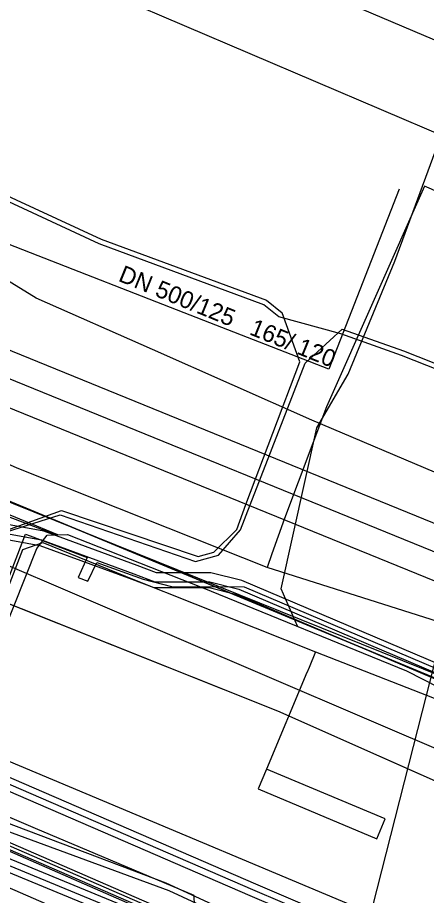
# Model space of a CAD drawing. Extents: x -596024 to -594475, y -1163820 to -1161957.
# Drawn here: x -594693.78 to -594674.72, y -1162231.56 to -1162190.62 of the extents above; entities that cross this region are included whole.
import ezdxf

# ---------------------------------------------------------------- set-up
doc = ezdxf.new("R2010")
doc.units = 0
for name, color, linetype in [('Level 1', 7, 'Continuous'), ('Vrstva 1', 7, 'Continuous'), ('Vrstva 10', 7, 'Continuous'), ('Vrstva 12', 7, 'Continuous'), ('Vrstva 13', 7, 'Continuous'), ('Vrstva 19', 7, 'Continuous'), ('Vrstva 29', 7, 'Continuous'), ('Vrstva 30', 7, 'Continuous'), ('Vrstva 32', 7, 'Continuous'), ('Vrstva 42', 7, 'Continuous'), ('Vrstva 44', 7, 'Continuous'), ('Vrstva 55', 7, 'Continuous'), ('Vrstva 58', 7, 'Continuous'), ('Vrstva 9', 7, 'Continuous')]:
    doc.layers.add(name, color=color, linetype=linetype)

msp = doc.modelspace()

# ---------------------------------------------------------------- linework, layer by layer
at = {"layer": 'Level 1'}
msp.add_lwpolyline([(-594750.45, -1162195.55), (-594709.77, -1162211.75), (-594681.66, -1162222.95), (-594639.16, -1162241.84), (-594604.2, -1162257.38), (-594561.16, -1162275.84)], dxfattribs=at)
at = {"layer": 'Vrstva 1'}
for points in [[(-594709.77, -1162211.75), (-594707.04, -1162212.84), (-594697.64, -1162216.58), (-594681.66, -1162222.95)], [(-594681.66, -1162222.95), (-594661.62, -1162231.86), (-594655.18, -1162234.72), (-594641.16, -1162240.95), (-594639.16, -1162241.84)]]:
    msp.add_lwpolyline(points, dxfattribs=at)
at = {"layer": 'Vrstva 10'}
for points in [[(-594718.121, -1162215.685), (-594682.698, -1162231.026), (-594673.018, -1162235.167), (-594642.251, -1162248.515)], [(-594642.489, -1162249.065), (-594673.256, -1162235.718), (-594682.935, -1162231.577), (-594718.359, -1162216.235)], [(-594669.097, -1162240.596), (-594676.92, -1162237.095), (-594687.944, -1162232.423), (-594698.459, -1162228.081), (-594703.881, -1162225.994), (-594707.851, -1162224.099), (-594708.531, -1162223.765)], [(-594669.343, -1162241.144), (-594677.16, -1162237.645), (-594688.176, -1162232.977), (-594698.681, -1162228.639), (-594704.119, -1162226.546), (-594708.109, -1162224.641), (-594708.769, -1162224.315)]]:
    msp.add_lwpolyline(points, dxfattribs=at)
at = {"layer": 'Vrstva 12'}
for points in [[(-594709.79, -1162161.71), (-594711.19, -1162161.15), (-594711.71, -1162161.2), (-594720.54, -1162182.38), (-594720.76, -1162182.87), (-594723.51, -1162188.28), (-594727.58, -1162199.36), (-594715.62, -1162204.79), (-594697, -1162212.84), (-594691.98, -1162214.75)], [(-594687.5, -1162206.1), (-594692.91, -1162203.71), (-594698.08, -1162200.54), (-594701.97, -1162199.62), (-594703.17, -1162199.89), (-594736.07, -1162186.08), (-594790.15, -1162162.04)], [(-594680.74, -1162219.01), (-594681.49, -1162217.26), (-594679.84, -1162209.75), (-594678.37, -1162207.25), (-594676.2, -1162201.98), (-594672.39, -1162191.66), (-594669.77, -1162185.57), (-594666.54, -1162176.61), (-594662.03, -1162166.78)], [(-594691.9, -1162214.74), (-594693.41, -1162214.13), (-594708.66, -1162207.82), (-594726.57, -1162199.83), (-594745.03, -1162192.17), (-594754.89, -1162188.06), (-594753.69, -1162185.32)], [(-594767.38, -1162194.31), (-594722.65, -1162213.34), (-594687.5, -1162228.11)], [(-594669.22, -1162240.87), (-594677.04, -1162237.37), (-594688.06, -1162232.7), (-594698.57, -1162228.36), (-594704, -1162226.27), (-594707.98, -1162224.37), (-594708.65, -1162224.04), (-594716.25, -1162220.76), (-594733.56, -1162213.39), (-594745.1, -1162208.5), (-594754.35, -1162204.63), (-594755.28, -1162204.24), (-594755.87, -1162204), (-594756.43, -1162203.77), (-594756.78, -1162203.62), (-594757.22, -1162203.43), (-594757.54, -1162203.32), (-594758.33, -1162202.96), (-594758.77, -1162202.76), (-594758.93, -1162202.52), (-594760.19, -1162200.82), (-594760.82, -1162199.87)], [(-594673.84, -1162212.04), (-594680.06, -1162209.4), (-594687.5, -1162206.1)], [(-594701.93, -1162231.57), (-594700.22, -1162232.12), (-594699.53, -1162232.3), (-594698.85, -1162231.48), (-594698.82, -1162230.28), (-594692.89, -1162215.39), (-594692.41, -1162214.76), (-594691.46, -1162214.73), (-594685.17, -1162217.2), (-594675.66, -1162221.09), (-594674.13, -1162221.87), (-594673.14, -1162222.77), (-594660.42, -1162228.26), (-594659.07, -1162228.75), (-594653.33, -1162230.97), (-594645.81, -1162234.32), (-594640.49, -1162236.32), (-594633.61, -1162239.41), (-594630.67, -1162240.39), (-594630.22, -1162240.14), (-594629.84, -1162239.45)], [(-594701.93, -1162231.57), (-594700.22, -1162232.12), (-594699.53, -1162232.3), (-594698.85, -1162231.48), (-594698.82, -1162230.28), (-594692.89, -1162215.39), (-594692.41, -1162214.76), (-594691.46, -1162214.73), (-594685.17, -1162217.2), (-594675.66, -1162221.09), (-594674.13, -1162221.87), (-594673.14, -1162222.77), (-594660.42, -1162228.26), (-594659.07, -1162228.75), (-594653.33, -1162230.97), (-594645.81, -1162234.32), (-594640.49, -1162236.32), (-594633.61, -1162239.41), (-594630.67, -1162240.39), (-594630.22, -1162240.14), (-594629.84, -1162239.45)], [(-594687.5, -1162228.11), (-594635.41, -1162250)]]:
    msp.add_lwpolyline(points, dxfattribs=at)
at = {"layer": 'Vrstva 13'}
msp.add_line((-594825.39, -1162131.442), (-594661.497, -1162201.455), dxfattribs=at)
for points in [[(-595078.908, -1162012.46), (-595067.73, -1162017.42), (-595065.08, -1162018.44), (-594997.08, -1162047.37), (-594955.55, -1162065.41), (-594939.29, -1162072.9), (-594936.52, -1162074.16), (-594923.87, -1162075.93), (-594910.2, -1162085.83), (-594902.18, -1162091.86), (-594900.73, -1162093.05), (-594899.52, -1162093.99), (-594898.81, -1162094.53), (-594891.57, -1162097.97), (-594883.253, -1162101.678), (-594870.37, -1162107.41), (-594778.03, -1162146.97), (-594708.7, -1162177.08), (-594658.923, -1162198.2)], [(-594836.23, -1162155.443), (-594836.196, -1162155.782), (-594816.247, -1162164.384), (-594814.935, -1162164.957), (-594803.879, -1162169.64), (-594755.473, -1162190.086), (-594744.01, -1162194.87), (-594731.121, -1162200.339), (-594730.015, -1162200.811), (-594704.47, -1162211.75), (-594699.45, -1162213.94), (-594673.314, -1162225.133)]]:
    msp.add_lwpolyline(points, dxfattribs=at)
at = {"layer": 'Vrstva 19'}
for points in [[(-594695.25, -1162276.17), (-594690.21, -1162265.28), (-594680.2, -1162243.33), (-594679.351, -1162240.241), (-594678.82, -1162238.33), (-594678.078, -1162235.421), (-594674.9, -1162222.97), (-594673.86, -1162218.9), (-594682.15, -1162216.27), (-594693.73, -1162211.66), (-594707.83, -1162205.54), (-594713.34, -1162203.16), (-594714.6, -1162202.61), (-594730.47, -1162196.31), (-594740.5, -1162192.55), (-594751.07, -1162187.95), (-594753.63, -1162189.06), (-594775.09, -1162179.85), (-594776.07, -1162176.84), (-594793.1, -1162168.81), (-594802.09, -1162164.76), (-594816.08, -1162158.49), (-594834.13, -1162150.42), (-594853.67, -1162141.96)], [(-594685.55, -1162231.56), (-594692.94, -1162228.45), (-594699.49, -1162225.65), (-594749.98, -1162204.19), (-594785.76, -1162188.98), (-594797.35, -1162184.05)], [(-594673.7, -1162198.99), (-594674.48, -1162198.63), (-594674.81, -1162198.49), (-594679.38, -1162208.77), (-594681.34, -1162213.98), (-594681.93, -1162215.63), (-594682.15, -1162216.27)], [(-594672.02, -1162237.58), (-594672.39, -1162237.76), (-594674.91, -1162239.83), (-594676.98, -1162240.84), (-594678.73, -1162240.33), (-594678.81, -1162240.31), (-594679.02, -1162240.26), (-594679.43, -1162240.18), (-594679.63, -1162240.15), (-594679.77, -1162240.12), (-594682.47, -1162239.25), (-594684.29, -1162236.54), (-594684.66, -1162235.21), (-594685.53, -1162232.03), (-594685.55, -1162231.56)]]:
    msp.add_lwpolyline(points, dxfattribs=at)
at = {"layer": 'Vrstva 29'}
msp.add_lwpolyline([(-594527.721, -1162116.547), (-594550.035, -1162144.733), (-594618.49, -1162117.698), (-594660.636, -1162221.142), (-594706.437, -1162202.481)], dxfattribs=at)
at = {"layer": 'Vrstva 30'}
for points in [[(-594706.74, -1162201.008), (-594661.322, -1162219.513), (-594619.181, -1162116.081), (-594550.439, -1162143.229), (-594528.701, -1162115.771)], [(-594526.741, -1162117.323), (-594549.631, -1162146.237), (-594617.799, -1162119.315), (-594659.95, -1162222.771), (-594706.133, -1162203.955)]]:
    msp.add_lwpolyline(points, dxfattribs=at)
at = {"layer": 'Vrstva 42'}
for points in [[(-594841.22, -1162164.89), (-594841.55, -1162165.818), (-594823.941, -1162173.342), (-594805.527, -1162181.255), (-594786.096, -1162189.732), (-594763.998, -1162199.133), (-594752.438, -1162204.617), (-594739.102, -1162210.309), (-594723.16, -1162216.972), (-594709.798, -1162222.556), (-594699.416, -1162226.808), (-594686.936, -1162232.243), (-594670.535, -1162239.442), (-594642.912, -1162251.21), (-594626.307, -1162258.207), (-594595.818, -1162271.123), (-594582.146, -1162276.922), (-594568.678, -1162282.65), (-594548.298, -1162291.531), (-594530.464, -1162298.451), (-594511.972, -1162306.232), (-594493.611, -1162313.902), (-594475.47, -1162321.871)], [(-594805, -1162180.3), (-594805.561, -1162181.567), (-594805.473, -1162181.605), (-594786.214, -1162190.008), (-594764.122, -1162199.407), (-594752.562, -1162204.891), (-594739.218, -1162210.585), (-594723.276, -1162217.248), (-594709.912, -1162222.834), (-594699.532, -1162227.084), (-594687.056, -1162232.517), (-594670.655, -1162239.718), (-594643.03, -1162251.486), (-594626.423, -1162258.483), (-594595.936, -1162271.399), (-594582.264, -1162277.198), (-594568.796, -1162282.926), (-594548.412, -1162291.809), (-594530.576, -1162298.729), (-594512.088, -1162306.508), (-594493.729, -1162314.178), (-594475.47, -1162322.199)], [(-594475.47, -1162322.035), (-594492.486, -1162314.56), (-594509.999, -1162307.221), (-594528.715, -1162299.349), (-594548.355, -1162291.67), (-594568.737, -1162282.788), (-594582.205, -1162277.06), (-594595.877, -1162271.261), (-594626.365, -1162258.345), (-594642.971, -1162251.348), (-594670.595, -1162239.58), (-594686.996, -1162232.38), (-594699.474, -1162226.946), (-594709.855, -1162222.695), (-594723.218, -1162217.11), (-594739.16, -1162210.447), (-594752.5, -1162204.754), (-594764.06, -1162199.27), (-594786.155, -1162189.87), (-594805.5, -1162181.43)], [(-594615.74, -1162262.79), (-594624.65, -1162259.07), (-594637.95, -1162253.48), (-594653.13, -1162246.96), (-594666.17, -1162241.28), (-594679.92, -1162235.52), (-594687.43, -1162232.45), (-594694.39, -1162229.4), (-594701, -1162226.48), (-594711.77, -1162221.9), (-594718.09, -1162219.27), (-594728.65, -1162214.76), (-594737.08, -1162211.18), (-594746.93, -1162206.99), (-594753.92, -1162203.71), (-594761.99, -1162200.35), (-594768.71, -1162197.49), (-594777.63, -1162193.65), (-594785.3, -1162190.25), (-594792.89, -1162187), (-594796.23, -1162185.84), (-594796.51, -1162185.77), (-594796.81, -1162185.85)], [(-594699.54, -1162231.03), (-594693.54, -1162215.43), (-594692.61, -1162215.1), (-594688.33, -1162216.85), (-594679.89, -1162220.2)], [(-594679.89, -1162220.2), (-594680.19, -1162220.93), (-594680.3, -1162221.18)], [(-594679.89, -1162220.2), (-594674.37, -1162222.37), (-594672.114, -1162223.265)], [(-594680.291, -1162221.159), (-594682.183, -1162225.678), (-594682.569, -1162226.6), (-594677.034, -1162228.917), (-594676.648, -1162227.995), (-594682.183, -1162225.678)]]:
    msp.add_lwpolyline(points, dxfattribs=at)
at = {"layer": 'Vrstva 44'}
for points in [[(-594615.489, -1162264.329), (-594617.876, -1162263.185), (-594624.753, -1162260.392), (-594653.042, -1162248.004), (-594673.87, -1162239.439), (-594676.32, -1162238.996), (-594700.937, -1162228.271), (-594701.517, -1162227.634), (-594706.4, -1162225.55), (-594708.626, -1162224.544), (-594732.851, -1162213.96), (-594749.58, -1162206.904), (-594751.558, -1162206.159), (-594757.592, -1162203.739), (-594760.561, -1162201.965), (-594774.949, -1162195.637), (-594776.33, -1162195.028), (-594780.641, -1162193.061), (-594785.301, -1162190.858), (-594797.218, -1162185.869), (-594798.27, -1162185.406), (-594820.513, -1162176.019), (-594846.169, -1162165.001), (-594853.363, -1162161.962)], [(-594717.114, -1162188.761), (-594696.98, -1162197.67), (-594689.88, -1162200.96), (-594682.185, -1162203.807), (-594681.454, -1162204.395)], [(-594710.511, -1162246.121), (-594706.724, -1162241.317), (-594700.171, -1162229.614), (-594694.505, -1162214.613), (-594691.734, -1162213.615), (-594685.364, -1162215.761), (-594684.632, -1162215.557), (-594683.554, -1162214.497), (-594683.14, -1162213.325), (-594680.629, -1162206.672), (-594681.454, -1162204.395)], [(-594710.389, -1162246.171), (-594706.656, -1162241.485), (-594700.077, -1162229.706), (-594694.291, -1162214.612), (-594691.804, -1162213.81), (-594685.493, -1162215.996), (-594684.419, -1162215.691), (-594683.384, -1162214.508), (-594682.942, -1162213.351), (-594680.38, -1162206.736), (-594678.644, -1162205.16)], [(-594678.644, -1162205.16), (-594675.8, -1162206.17), (-594668.05, -1162209.23), (-594663.13, -1162210.88), (-594651.32, -1162215.21), (-594641.28, -1162219.24), (-594633.977, -1162221.217), (-594633.824, -1162221.643), (-594634.056, -1162222.424)], [(-594614.41, -1162261.91), (-594621.99, -1162258.58), (-594628.37, -1162255.68), (-594636.04, -1162252.82), (-594642.94, -1162249.7), (-594656.3, -1162244), (-594663.1, -1162240.9), (-594670.56, -1162238.06), (-594678.56, -1162234.81), (-594686.86, -1162230.99), (-594695.45, -1162227.75), (-594696.12, -1162227.93), (-594696.75, -1162228.24), (-594697.24, -1162228.82), (-594697.77, -1162230.04), (-594699.66, -1162234.68), (-594702.47, -1162240.02), (-594704.27, -1162242.54), (-594705.7, -1162243.65), (-594707.64, -1162244.5), (-594708.77, -1162244.96), (-594709.91, -1162246.4), (-594710.539, -1162247.725)], [(-594710.243, -1162247.851), (-594709.62, -1162246.52), (-594708.65, -1162245.21), (-594707.44, -1162244.71), (-594705.54, -1162243.89), (-594704.05, -1162242.67), (-594702.2, -1162240.18), (-594699.38, -1162234.79), (-594697.5, -1162230.19), (-594696.67, -1162228.8), (-594696.02, -1162228.26), (-594695.41, -1162228.16), (-594695.4, -1162228.15), (-594686.73, -1162231.34), (-594678.69, -1162235.07), (-594670.68, -1162238.26), (-594662.6, -1162241.59), (-594656.44, -1162244.41), (-594643.09, -1162250), (-594636.37, -1162253.13), (-594628.37, -1162256.91), (-594622.62, -1162258.99), (-594614.48, -1162262.29)]]:
    msp.add_lwpolyline(points, dxfattribs=at)
at = {"layer": 'Vrstva 55'}
for points in [[(-594676, -1162198.63), (-594679.27, -1162207.02), (-594686.021, -1162204.388), (-594693.174, -1162201.599), (-594697.76, -1162199.81)], [(-594736.35, -1162216.17), (-594730, -1162218.88), (-594723.92, -1162221.75), (-594722.26, -1162222.11), (-594720.99, -1162223.06), (-594709.27, -1162228.95), (-594702.94, -1162230.72), (-594700.4, -1162231.47), (-594699.21, -1162229.78), (-594693.41, -1162214.71), (-594693.19, -1162214.79), (-594690.54, -1162215.81), (-594690.95, -1162216.73), (-594690.51, -1162216.9), (-594690.08, -1162216.03), (-594687.93, -1162216.81), (-594686.61, -1162217.15), (-594683.22, -1162217.17), (-594671.84, -1162222)]]:
    msp.add_lwpolyline(points, dxfattribs=at)
at = {"layer": 'Vrstva 58'}
for points in [[(-594855.8, -1162145.62), (-594837.62, -1162153.37), (-594836.31, -1162153.98), (-594819.51, -1162161.12), (-594801.35, -1162168.87), (-594799.77, -1162169.48), (-594797.27, -1162170.37), (-594784.28, -1162175.73), (-594782.11, -1162176.71), (-594778.76, -1162179.27), (-594754.53, -1162189.16), (-594752.65, -1162189.31), (-594750.57, -1162189.75), (-594747.53, -1162190.99), (-594651.85, -1162230.77), (-594634.34, -1162238.31), (-594628.08, -1162237.31), (-594627.27, -1162237.69), (-594626.17, -1162238.17), (-594617.89, -1162242.16), (-594607.87, -1162246.62)], [(-594855.521, -1162146.975), (-594837.445, -1162154.525), (-594819.368, -1162162.393), (-594800.867, -1162170.155), (-594782.472, -1162177.705), (-594753.124, -1162190.465), (-594723.671, -1162201.842), (-594694.961, -1162212.9), (-594661.467, -1162226.404), (-594631.163, -1162239.589), (-594604.155, -1162251.18), (-594572.468, -1162264.684), (-594547.693, -1162277.762), (-594525.576, -1162287.119), (-594507.394, -1162294.988), (-594488.786, -1162302.856), (-594475.47, -1162308.493)], [(-594668.127, -1162209.442), (-594675.879, -1162206.381), (-594678.72, -1162205.373), (-594681.602, -1162204.579), (-594682.303, -1162204.015), (-594689.971, -1162201.178), (-594697.077, -1162197.885), (-594717.209, -1162188.976), (-594720.048, -1162188.083), (-594726.916, -1162184.938), (-594734.962, -1162181.502), (-594740.391, -1162178.33), (-594743.065, -1162176.746), (-594745.465, -1162176.293), (-594746.491, -1162175.638), (-594749.931, -1162174.314), (-594754.673, -1162172.449), (-594762.484, -1162168.904), (-594769.821, -1162165.535)], [(-594672.766, -1162221.374), (-594683.334, -1162216.877), (-594684.767, -1162216.516), (-594687.303, -1162216.516), (-594688.212, -1162216.173), (-594692.558, -1162214.57), (-594694.598, -1162214.201), (-594695.817, -1162214.059), (-594700.524, -1162211.418), (-594703.584, -1162210.146), (-594706.857, -1162208.909), (-594717.881, -1162203.895), (-594719.923, -1162202.648), (-594721.529, -1162201.453), (-594724.084, -1162200.028), (-594728.833, -1162198.03), (-594730.767, -1162197.189), (-594742.598, -1162192.46), (-594744.999, -1162190.966), (-594753.516, -1162187.044), (-594754.999, -1162186.388), (-594770.392, -1162180.507)], [(-594770.779, -1162181.097), (-594755.261, -1162187.025), (-594753.799, -1162187.672), (-594745.326, -1162191.574), (-594742.91, -1162193.078), (-594731.032, -1162197.825), (-594729.104, -1162198.664), (-594724.386, -1162200.649), (-594721.904, -1162202.033), (-594720.309, -1162203.22), (-594718.204, -1162204.505), (-594707.122, -1162209.545), (-594703.838, -1162210.787), (-594700.826, -1162212.039), (-594696.033, -1162214.727), (-594694.699, -1162214.883), (-594692.74, -1162215.237), (-594688.453, -1162216.819), (-594687.428, -1162217.205), (-594684.853, -1162217.205), (-594683.555, -1162217.532), (-594672.935, -1162222.05)], [(-594770.63, -1162180.87), (-594755.16, -1162186.78), (-594753.69, -1162187.43), (-594745.2, -1162191.34), (-594742.79, -1162192.84), (-594730.93, -1162197.58), (-594729, -1162198.42), (-594724.27, -1162200.41), (-594721.76, -1162201.81), (-594720.16, -1162203), (-594718.08, -1162204.27), (-594707.02, -1162209.3), (-594703.74, -1162210.54), (-594700.71, -1162211.8), (-594695.95, -1162214.47), (-594694.66, -1162214.62), (-594692.67, -1162214.98), (-594688.36, -1162216.57), (-594687.38, -1162216.94), (-594684.82, -1162216.94), (-594683.47, -1162217.28), (-594672.87, -1162221.79)], [(-594770.63, -1162180.87), (-594755.16, -1162186.78), (-594753.69, -1162187.43), (-594745.2, -1162191.34), (-594742.79, -1162192.84), (-594730.93, -1162197.58), (-594729, -1162198.42), (-594724.27, -1162200.41), (-594721.76, -1162201.81), (-594720.16, -1162203), (-594718.08, -1162204.27), (-594707.02, -1162209.3), (-594703.74, -1162210.54), (-594700.71, -1162211.8), (-594695.95, -1162214.47), (-594694.66, -1162214.62), (-594692.67, -1162214.98), (-594688.36, -1162216.57), (-594687.38, -1162216.94), (-594684.82, -1162216.94), (-594683.47, -1162217.28), (-594672.87, -1162221.79)], [(-594606.25, -1162247.31), (-594607.87, -1162246.62), (-594617.89, -1162242.16), (-594626.17, -1162238.17), (-594627.27, -1162237.69), (-594628.08, -1162237.31), (-594634.34, -1162238.31), (-594651.85, -1162230.77), (-594747.53, -1162190.99), (-594750.57, -1162189.75)]]:
    msp.add_lwpolyline(points, dxfattribs=at)
at = {"layer": 'Vrstva 9'}
msp.add_lwpolyline([(-594642.37, -1162248.79), (-594673.137, -1162235.442), (-594682.817, -1162231.302), (-594718.24, -1162215.96)], dxfattribs=at)

# ---------------------------------------------------------------- texts
at = {"layer": 'Vrstva 32'}
msp.add_text('DN 500/125   165/ 120', height=0.8, rotation=337.8159, dxfattribs=at).set_placement((-594689.13, -1162202.891))

doc.saveas('drawing.dxf')
